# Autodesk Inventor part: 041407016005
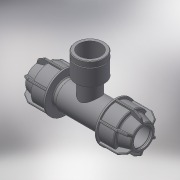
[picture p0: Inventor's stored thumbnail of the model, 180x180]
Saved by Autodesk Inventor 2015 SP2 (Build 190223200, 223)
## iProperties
Created: 2017-08
Part Number: 041407016005
Material: Generic
Description: PLASSON IRRIFIT TEE FEMALE ADAPTOR 16-1/2"-16
Document SubType Name: Modeling
Designer: KIM
Density: 1 g/cm^3
Appearance: Default
Author: KIM
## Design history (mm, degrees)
derived "041407.ipt"
feature "Solid1::041407.ipt"
feature "Solid2::041407.ipt"
tag "TaggingFeature1"
body "Solid1"
other parameters: "d1" = 16, "d2" = 25, "d4" = 15 deg, "d5" = 23.75, "d6" = 9.5, "d10" = 34, "d16" = 16.32, "d17" = 1.25, "d22" = 20.8, "d24" = 1.25, "d25" = 30.6, "d26" = 25.5, "d27" = 1.25, "d28" = 135 deg, "d29" = 0.75, "d31" = 0.8, "d46" = 150 deg, "d49" = 1.7, "d50" = 0, "d58" = 0.48, "d61" = 360 deg, "d63" = 14.4, "d64" = 45, "d80" = 22.88, "d81" = 0.16, "d94" = 42, "d96" = 24.2203, "d108" = 0.48, "d113" = 13.0417, "d115" = 19.2, "d117" = 16.7679, "d118" = 2.5, "d119" = 16, "d120" = 18.631, "d121" = 0.37262, "d122" = 4.8, "d123" = 2.5, "d128" = 24.2203, "d130" = 0, "d132" = 0, "d_" = 16, "G_" = 18.631, "E_" = 34, "l_" = 25, "l_1" = 16, "A_" = 42
